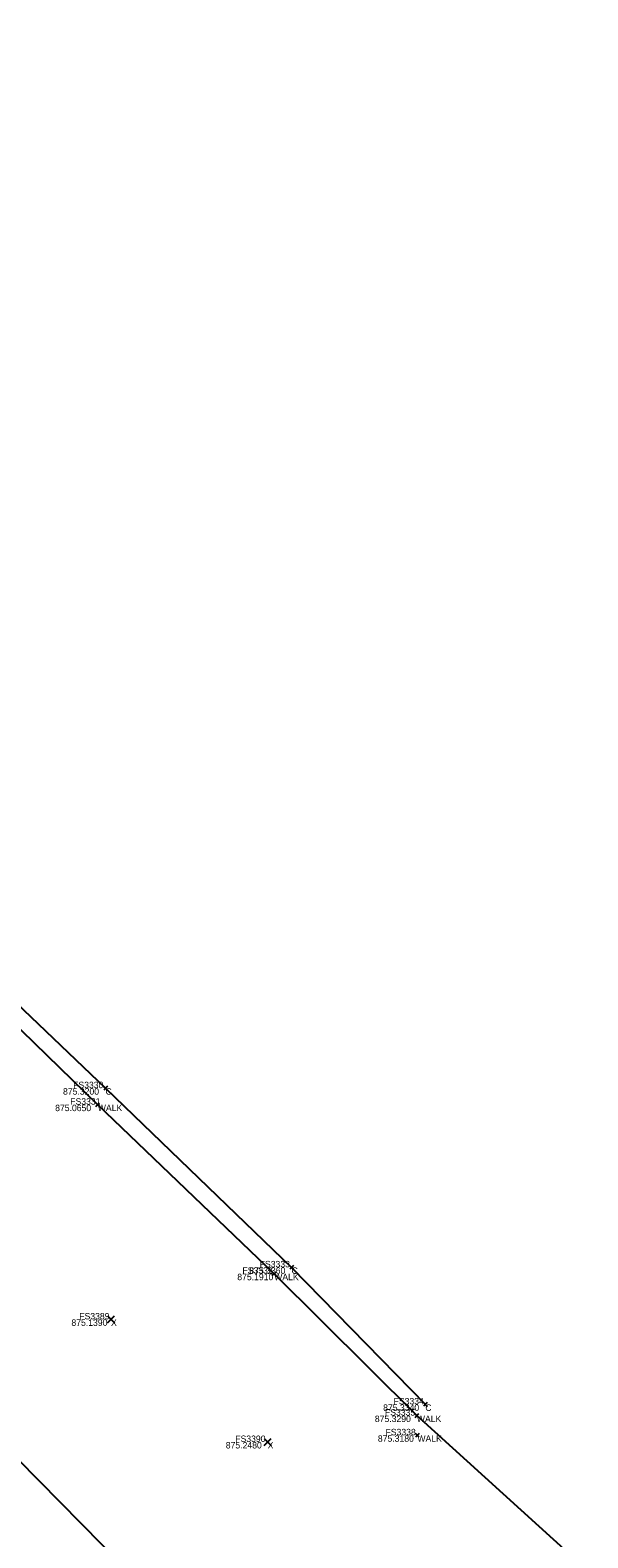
# Model space of a CAD drawing. Extents: x 1479481 to 1575806, y 316056 to 379927.
# Drawn here: x 1480221.81 to 1480226.99, y 379409.43 to 379423.43 of the extents above; entities that cross this region are included whole.
import ezdxf

# ---------------------------------------------------------------- set-up
doc = ezdxf.new("R2010")
doc.units = 0
for name, color, linetype in [('PV_X_Curb', 7, 'Continuous'), ('PV_X_Walk', 7, 'Continuous'), ('SV_X_Random_Point', 7, 'Continuous'), ('SV_X_Shot_Marker', 7, 'Continuous'), ('SV_X_Text_Comment', 7, 'Continuous'), ('SV_X_Text_Elevation', 7, 'Continuous'), ('SV_X_Text_Name', 7, 'Continuous'), ('UT_X_Water', 7, 'Continuous')]:
    doc.layers.add(name, color=color, linetype=linetype)

msp = doc.modelspace()

# ---------------------------------------------------------------- linework, layer by layer
at = {"layer": 'PV_X_Curb'}
msp.add_lwpolyline([(1480212.291, 379423.24), (1480213.594, 379422.019), (1480215.401, 379420.362), (1480217.251, 379418.639), (1480219.182, 379416.756), (1480220.704, 379415.328), (1480222.514, 379413.605), (1480224.242, 379411.942), (1480225.485, 379410.67)], dxfattribs=at)
at = {"layer": 'PV_X_Walk'}
msp.add_lwpolyline([(1480235.613, 379401.335), (1480225.406, 379410.566), (1480224.081, 379411.883), (1480222.442, 379413.452), (1480220.637, 379415.199), (1480219.083, 379416.674), (1480217.151, 379418.526), (1480213.465, 379422.054), (1480212.267, 379423.157), (1480197.466, 379437.463), (1480177.803, 379455.97), (1480154.79, 379476.967), (1480132.747, 379497.48), (1480113.376, 379516.728), (1480110.754, 379519.04), (1480109.877, 379518.336), (1480091.944, 379535.267), (1480093.027, 379536.619), (1480090.219, 379539.243), (1480090.463, 379539.725), (1480084.681, 379544.882), (1480083.843, 379544.144), (1480066.818, 379560.524), (1480045.662, 379580.046)], dxfattribs=at)
at = {"layer": 'SV_X_Random_Point'}
for p, q in [((1480222.532, 379411.426), (1480222.598, 379411.492)), ((1480222.532, 379411.492), (1480222.598, 379411.426)), ((1480223.987, 379410.288), (1480224.053, 379410.354)), ((1480223.987, 379410.354), (1480224.053, 379410.288))]:
    msp.add_line(p, q, dxfattribs=at)
at = {"layer": 'SV_X_Shot_Marker'}
for p, q in [((1480222.496, 379413.622), (1480222.532, 379413.588)), ((1480222.531, 379413.623), (1480222.497, 379413.587)), ((1480222.514, 379413.605), (1480222.514, 379413.605)), ((1480222.46, 379413.435), (1480222.424, 379413.469)), ((1480222.425, 379413.434), (1480222.459, 379413.47)), ((1480222.442, 379413.452), (1480222.442, 379413.452)), ((1480224.063, 379411.865), (1480224.099, 379411.901)), ((1480224.099, 379411.865), (1480224.063, 379411.901)), ((1480224.081, 379411.883), (1480224.081, 379411.883)), ((1480224.224, 379411.959), (1480224.26, 379411.925)), ((1480224.259, 379411.96), (1480224.225, 379411.924)), ((1480224.242, 379411.942), (1480224.242, 379411.942)), ((1480225.425, 379410.549), (1480225.387, 379410.583)), ((1480225.389, 379410.547), (1480225.423, 379410.585)), ((1480225.406, 379410.566), (1480225.406, 379410.566)), ((1480225.503, 379410.687), (1480225.467, 379410.653)), ((1480225.468, 379410.688), (1480225.502, 379410.652)), ((1480225.485, 379410.67), (1480225.485, 379410.67)), ((1480225.429, 379410.366), (1480225.393, 379410.4)), ((1480225.428, 379410.401), (1480225.394, 379410.365)), ((1480225.411, 379410.383), (1480225.411, 379410.383))]:
    msp.add_line(p, q, dxfattribs=at)
at = {"layer": 'UT_X_Water'}
msp.add_lwpolyline([(1480224.057, 379407.77), (1480199.329, 379432.864)], dxfattribs=at)

# ---------------------------------------------------------------- texts
at = {"layer": 'SV_X_Text_Comment'}
for s, p in [('C', (1480222.514, 379413.545)), ('WALK', (1480222.442, 379413.392)), ('WALK', (1480224.081, 379411.823)), ('C', (1480224.242, 379411.882)), ('X', (1480222.565, 379411.399)), ('WALK', (1480225.406, 379410.506)), ('C', (1480225.485, 379410.61)), ('X', (1480224.02, 379410.261)), ('WALK', (1480225.411, 379410.323))]:
    msp.add_text(s, height=0.06, dxfattribs=at).set_placement(p)
at = {"layer": 'SV_X_Text_Elevation'}
for s, p in [('875.3200', (1480222.119, 379413.545)), ('875.0650', (1480222.046, 379413.392)), ('875.1910', (1480223.738, 379411.823)), ('875.3360', (1480223.85, 379411.882)), ('875.1390', (1480222.197, 379411.399)), ('875.3290', (1480225.016, 379410.506)), ('875.3340', (1480225.093, 379410.61)), ('875.2480', (1480223.631, 379410.261)), ('875.3180', (1480225.044, 379410.323))]:
    msp.add_text(s, height=0.06, dxfattribs=at).set_placement(p)
at = {"layer": 'SV_X_Text_Name'}
for s, p in [('FS3330', (1480222.213, 379413.605)), ('FS3331', (1480222.186, 379413.452)), ('FS3333', (1480223.946, 379411.942)), ('FS3332', (1480223.786, 379411.883)), ('FS3389', (1480222.27, 379411.459)), ('FS3334', (1480225.19, 379410.67)), ('FS3335', (1480225.11, 379410.566)), ('FS3338', (1480225.115, 379410.383)), ('FS3390', (1480223.719, 379410.321))]:
    msp.add_text(s, height=0.06, dxfattribs=at).set_placement(p)

doc.saveas('drawing.dxf')
